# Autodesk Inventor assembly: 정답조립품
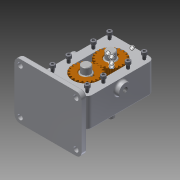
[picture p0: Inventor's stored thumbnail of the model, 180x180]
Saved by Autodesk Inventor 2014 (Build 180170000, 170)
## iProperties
Created: 2020-04
Part Number: 정답조립품
Document SubType Name: Assembly
Designer: kh
Author: kh
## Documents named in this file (11)
- C:\Users\kh\Desktop\700407V1058\정답조립품.iam
- C:\Users\kh\Desktop\700407V1058\본체.ipt
- C:\Users\kh\Desktop\700407V1058\Ű 6 x 6 x 18.ipt
- C:\Users\kh\Desktop\700407V1058\개스킷.ipt
- C:\Users\kh\Desktop\700407V1058\메인축.ipt
- C:\Users\kh\Desktop\700407V1058\베어링부시.ipt
- C:\Users\kh\Desktop\700407V1058\볼트 M5.ipt
- C:\Users\kh\Desktop\700407V1058\서브축.ipt
- C:\Users\kh\Desktop\700407V1058\스퍼기어.ipt
- C:\Users\kh\Desktop\700407V1058\오일 실 16 28 7.ipt
- C:\Users\kh\Desktop\700407V1058\커버.ipt
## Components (3 placed, 2 different names)
1. Ű 6 x 6 x 18:1 — 각도:1
2. 개스킷:1 — 플러쉬:1, 플러쉬:2
3. Ű 6 x 6 x 18:2 — 각도:2
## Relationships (4: Angle 2, Flush 2)
- 각도:1 [Angle]: Ű 6 x 6 x 18:1
- 각도:2 [Angle]: Ű 6 x 6 x 18:2
- 플러쉬:1 [Flush]: 개스킷:1
- 플러쉬:2 [Flush]: 개스킷:1
